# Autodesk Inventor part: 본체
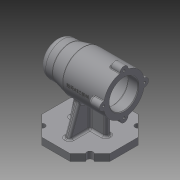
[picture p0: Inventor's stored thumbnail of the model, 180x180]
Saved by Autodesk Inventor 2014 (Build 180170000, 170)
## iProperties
Created: 2021-01
Part Number: 본체
Material: Generic
Document SubType Name: Modeling
Designer: kh
Density: 1 g/cm^3
Appearance: Default
Author: kh
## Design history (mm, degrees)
sketch "Sketch1" dims "d1" = 100
  geometry: L1 (0, 0)-(0, 50); L2 (20.711, 50)-(50, 20.711); L3 (50, 20.711)-(50, -20.711); L4 (50, -20.711)-(20.711, -50); L5 (20.711, -50)-(-20.711, -50); L6 (-20.711, -50)-(-50, -20.711); L7 (-50, -20.711)-(-50, 20.711); L8 (-50, 20.711)-(-20.711, 50); L9 (-20.711, 50)-(20.711, 50); 2 further points
  constraints: 18 end point, 2 coincident, 1 midpoint, 1 vertical, 1 vertical alignment, 19 other
extrude "Extrusion1" new body sketch "Sketch1" distance "d2" = 10; taper "d3" = 0 deg
sketch "Sketch2"
  geometry: L1 (0, 0)-(50, 0); L2 (0, 0)-(35.355, 35.355); C1 r 4.5 at (35.355, 35.355); C2 r 4.5 at (-35.355, 35.355); C3 r 4.5 at (-35.355, -35.355); C4 r 4.5 at (35.355, -35.355); A1 r 50 centre (0, 0) between (50, 0) and (35.355, 35.355); 1 further point
  constraints: 5 centre point, 4 end point, 2 coincident, 2 point on circle, 1 horizontal, 9 other
  dimensions: "d4" = 100 diameter of A1; "d5" = 45 deg angle of L1 L2; "d6" = 9 diameter of C1; "d9" = 360 deg dimension on point (0, 0) C1.centre (derived)
extrude "Extrusion2" cut sketch "Sketch2" distance "d11" = 10; taper "d12" = 0 deg
sketch "Sketch3"
  geometry: L1 (20.711, 0)-(-20.711, 0) reference; L2 (0, 0)-(0, 75); L3 (50, 75)-(-50, 75); L4 (50, 75)-(50, 100); L5 (50, 100)-(30, 100); L6 (30, 100)-(10, 105); L7 (10, 105)-(-50, 105); L8 (-50, 105)-(-50, 75); L9 (-50, 96)-(-35, 96); L10 (-35, 96)-(-35, 99); L11 (-35, 99)-(7, 99); L12 (7, 99)-(7, 96); L13 (7, 96)-(19, 96); L14 (19, 96)-(19, 92.5); L15 (19, 92.5)-(37, 92.5); L16 (37, 92.5)-(37, 91); L17 (37, 91)-(41, 91); L18 (41, 91)-(41, 85.5); L19 (41, 85.5)-(44, 85.5); L20 (44, 85.5)-(44, 75)
  constraints: 38 end point, 12 perpendicular, 6 parallel, 2 point on line, 1 midpoint
  dimensions: "d13" = 75 distance of L2.end L2.start; "d14" = 100 distance of L3.start L3.end; "d15" = 20 distance from line of L5.end L4; "d16" = 40 distance from line of L6.end L4; "d17" = 50 diameter of L5 L3; "d18" = 60 diameter of L7 L3; "d19" = 42 diameter of L9 L3; "d20" = 48 diameter of L11 L3; "d21" = 42 diameter of L13 L3; "d22" = 35 diameter of L15 L3; "d23" = 32 diameter of L17 L3; "d24" = 21 diameter of L19 L3; "d25" = 15 distance of L9.start L9.end; "d26" = 42 distance of L10.end L11.end; "d27" = 12 distance of L12.end L13.end; "d28" = 18 distance of L14.end L15.end; "d29" = 4 distance of L16.end L17.end; "d30" = 3 distance of L18.end L19.end
revolve "Revolution1" sketch "Sketch3" stored, may be unused: angle "d31" = 90 deg
fillet "Fillet1" dims "d32" = 3
fillet "Fillet2" dims "d33" = 0.3
fillet "Fillet3" dims "d34" = 3
chamfer "Chamfer1" distance "d35" = 1; stored, may be unused: second distance "d36" = 2, angle "d37" = 45 deg
sketch "Sketch4"
  geometry: L1 (0, 0)-(-30, 0); C1 r 6 at (-30, 0); 1 further point
  constraints: 2 end point, 1 centre point, 1 coincident, 1 horizontal, 1 horizontal alignment, 1 other
  dimensions: "d39" = 12 diameter of C1
extrude "Extrusion3" join sketch "Sketch4" distance "d40" = 16; taper "d41" = 0 deg
pattern_circular "Circular Pattern1" dims angle "d43" = 360 deg
hole "Hole1" diameter "d47" = 3.242; stored, may be unused: countersink angle "d51" = 90 deg, drill point angle "d53" = 118 deg; dims "d45" = 10, "d46" = 10, "d48" = 8, "d49" = 4, "d50" = 2, "d52" = 10
pattern_circular "Circular Pattern2" dims angle "d55" = 360 deg
fillet "Fillet4" dims "d57" = 10
sketch "Sketch5"
  geometry: L1 (-4, -4)-(4, -4); L2 (4, -4)-(4, 4); L3 (4, 4)-(-4, 4); L4 (-4, 4)-(-4, -4); L5 (-4, -4)-(4, 4); L6 (4, -4)-(-4, 4); 1 further point
  constraints: 12 end point, 2 midpoint, 2 parallel, 1 horizontal, 1 perpendicular
  dimensions: "d60" = 8 distance of L2.end L3.end; "d61" = 8 distance of L1.end L2.end
extrude "Extrusion4" join sketch "Sketch5" stored distance "d62" = 16; taper "d63" = 0 deg
sketch "Sketch6"
  geometry: L1 (-50, 10)-(-38.537, 10) reference; L2 (-38.537, 10)-(-30.855, 10) reference; L3 (-27, 10)-(-27, 35.493); 2 further points
  constraints: 2 end point, 1 perpendicular, 1 point on line
  dimensions: "d64" = 23 distance of L1.start L3.start
feature "Rib1" sketch "Sketch6" dims "d65" = 1, "d66" = 8, "d67" = 0, "d68" = 0, "d69" = 1, "d70" = 1
sketch "Sketch7"
  geometry: L1 (38.537, 10)-(50, 10) reference; L2 (27, 10)-(22.664, 32.309); 1 further point
  constraints: 2 end point, 1 point on line
  dimensions: "d71" = 23 distance of L2.start L1.end; "d72" = 101 deg angle of L2 L1
feature "Rib2" sketch "Sketch7" dims "d73" = 1, "d74" = 8, "d75" = 0, "d76" = 0, "d77" = 1, "d78" = 1
sketch "Sketch8"
  geometry: L1 (50, 10)-(38.537, 10) reference; L2 (35, 10)-(27.043, 31.861); 1 further point
  constraints: 2 end point, 1 point on line
  dimensions: "d79" = 15 distance of L1.start L2.start; "d80" = 110 deg angle of L2 L1
feature "Rib3" sketch "Sketch8" dims "d81" = 1, "d82" = 8, "d83" = 0, "d84" = 0, "d85" = 1, "d86" = 1
mirror "Mirror1"
fillet "Fillet5" dims "d87" = 3
fillet "Fillet6" dims "d88" = 1
fillet "Fillet7" dims "d89" = 3
fillet "Fillet8" dims "d90" = 3
fillet "Fillet9" dims "d91" = 3
fillet "Fillet10" dims "d92" = 3
workplane "Work Plane1"
sketch "Sketch9"
  geometry: L1 (-24.592, 2.402)-(8.592, 2.402); L2 (8.592, 2.402)-(8.592, -2.402); L3 (8.592, -2.402)-(-24.592, -2.402); L4 (-24.592, -2.402)-(-24.592, 2.402); L5 (-8, 2.402)-(-8, -2.402); L6 (-24.592, 0)-(-8, 0); L7 (30, 36)-(30, 30.171) reference; L8 (-60, 25)-(-60, -25) reference; L9 (-60, 0)-(8.592, 0); 1 further point
  constraints: 6 end point, 5 midpoint, 1 perpendicular, 1 point on line, 2 other
  dimensions: "d93" = 38 distance from line of L5.start L7
emboss "Emboss1" sketch "Sketch9" dims "d1" = 100, "d4" = 100, "d5" = 45 deg, "d6" = 9, "d9" = 360 deg (derived), "d94" = 0.5, "d95" = 0
body "Solid1"
